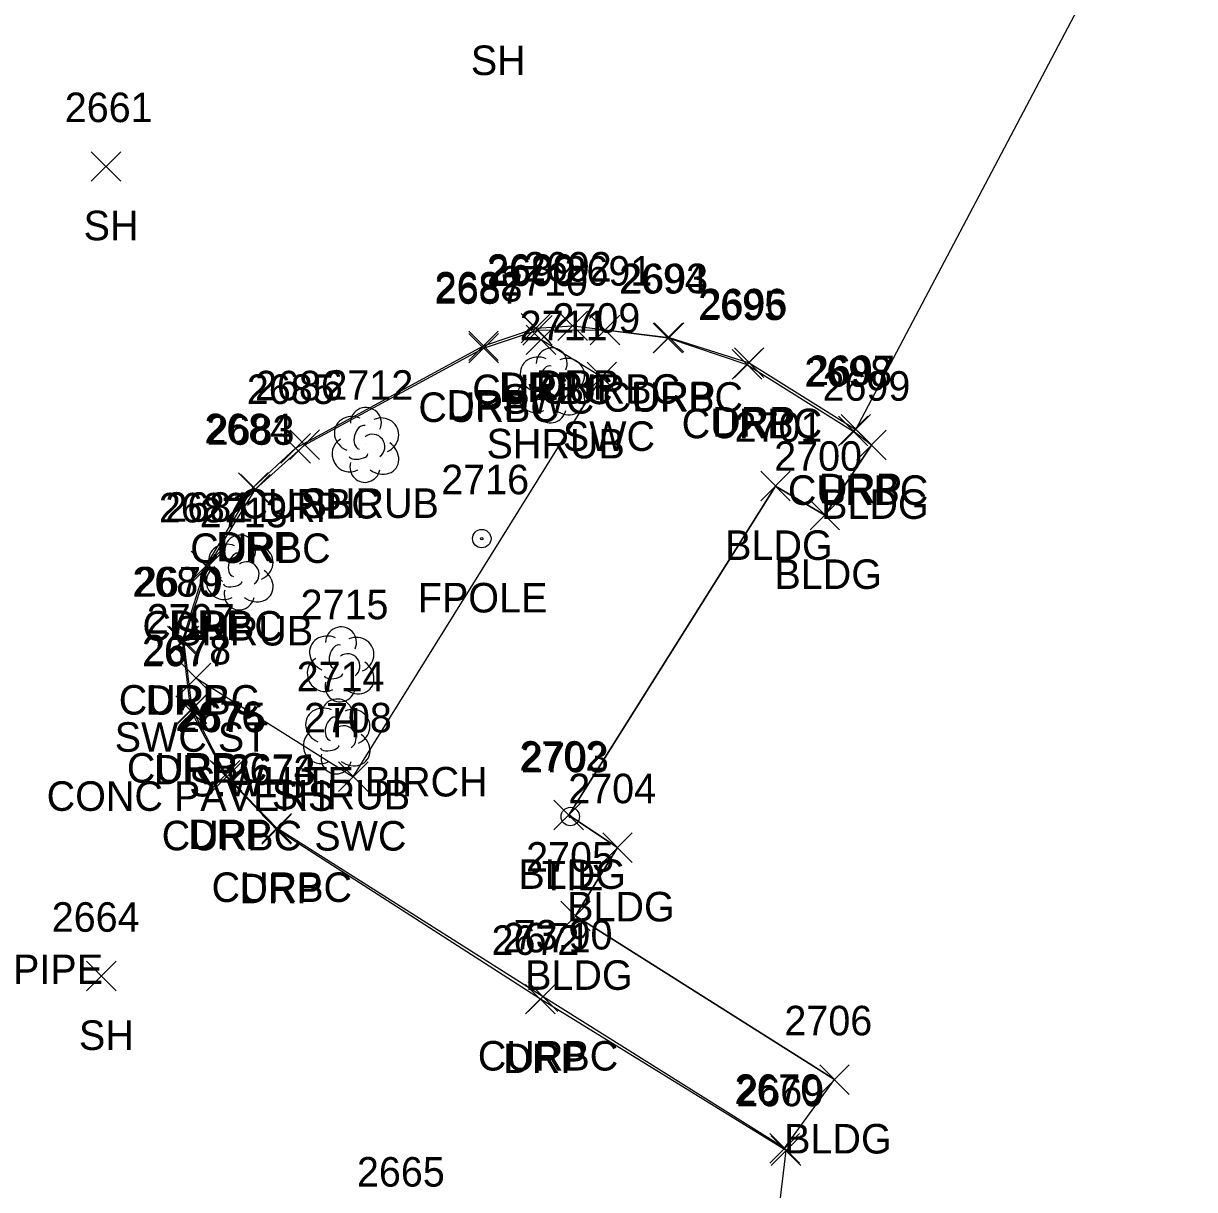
# Model space of a CAD drawing. Extents: x 1769141 to 1770911, y 735471 to 741449.
# Drawn here: x 1770697.4 to 1770776.7, y 737070.7 to 737149.7 of the extents above; entities that cross this region are included whole.
import ezdxf

# ---------------------------------------------------------------- set-up
doc = ezdxf.new("R2010")
doc.units = 0
for name, color, linetype in [('C_A', 7, 'Continuous'), ('C_C', 7, 'Continuous'), ('C_I', 7, 'Continuous'), ('CBP', 7, 'Continuous'), ('D_C', 7, 'Continuous'), ('L_A', 7, 'Continuous'), ('L_C', 7, 'Continuous'), ('L_I', 7, 'Continuous'), ('L_TIC', 7, 'Continuous'), ('LBC', 7, 'Continuous'), ('LFP', 7, 'Continuous'), ('LSH', 7, 'Continuous'), ('LSOGP', 7, 'Continuous'), ('LTD', 7, 'Continuous'), ('R_A', 7, 'Continuous'), ('R_C', 7, 'Continuous'), ('R_I', 7, 'Continuous'), ('R_TIC', 7, 'Continuous'), ('RC', 7, 'Continuous'), ('RDP', 7, 'Continuous'), ('RSW', 7, 'Continuous')]:
    doc.layers.add(name, color=color, linetype=linetype)

msp = doc.modelspace()

# ---------------------------------------------------------------- linework, layer by layer
at = {"layer": 'CBP'}
for radius in [0.625, 0.0833]:
    msp.add_circle((1770734.388, 737095.961), radius, dxfattribs=at)
at = {"layer": 'L_TIC'}
for points in [[(1770701.944, 737138.979), (1770703.944, 737140.979)], [(1770703.944, 737138.979), (1770701.944, 737140.979)], [(1770753.785, 737120.115), (1770755.785, 737122.115)], [(1770755.785, 737120.115), (1770753.785, 737122.115)], [(1770747.286, 737117.337), (1770749.286, 737119.337)], [(1770749.286, 737117.337), (1770747.286, 737119.337)], [(1770750.624, 737115.373), (1770752.624, 737117.373)], [(1770752.624, 737115.373), (1770750.624, 737117.373)], [(1770733.283, 737095.064), (1770735.283, 737097.064)], [(1770735.283, 737095.064), (1770733.283, 737097.064)], [(1770736.589, 737092.861), (1770738.589, 737094.861)], [(1770738.589, 737092.861), (1770736.589, 737094.861)], [(1770733.739, 737088.229), (1770735.739, 737090.229)], [(1770735.739, 737088.229), (1770733.739, 737090.229)], [(1770701.627, 737084.16), (1770703.627, 737086.16)], [(1770703.627, 737084.16), (1770701.627, 737086.16)], [(1770751.282, 737077.148), (1770753.282, 737079.148)], [(1770753.282, 737077.148), (1770751.282, 737079.148)]]:
    msp.add_lwpolyline(points, dxfattribs=at)
at = {"layer": 'LBC'}
msp.add_lwpolyline([(1770754.785, 737121.115), (1770751.624, 737116.373), (1770748.286, 737118.337), (1770734.283, 737096.064), (1770737.589, 737093.861), (1770734.739, 737089.229), (1770752.282, 737078.148)], dxfattribs=at)
at = {"layer": 'LFP'}
for radius in [0.625, 0.0833]:
    msp.add_circle((1770728.396, 737114.781), radius, dxfattribs=at)
at = {"layer": 'LSH'}
for p, q in [((1770733.087, 737125.212), (1770733.087, 737125.212)), ((1770733.087, 737125.212), (1770733.087, 737125.212)), ((1770720.501, 737121.18), (1770720.501, 737121.18)), ((1770720.501, 737121.18), (1770720.501, 737121.18)), ((1770711.987, 737112.544), (1770711.987, 737112.544)), ((1770711.987, 737112.544), (1770711.987, 737112.544)), ((1770718.551, 737101.44), (1770718.551, 737101.44)), ((1770718.551, 737101.44), (1770718.551, 737101.44))]:
    msp.add_line(p, q, dxfattribs=at)
for centre in [(1770733.134, 737126.646), (1770720.547, 737122.614), (1770712.034, 737113.978), (1770718.598, 737102.874)]:
    msp.add_arc(centre, 1.047, 335.52715, 180.95627, dxfattribs=at)
for centre, major_axis, ratio, start_param, end_param in [((1770732.295, 737125.879), (1.21, -0.512), 0.895232, 1.570796, 4.712389), ((1770734.129, 737125.796), (-1.141, -0.483), 0.949671, 1.570796, 4.712389), ((1770732.879, 737125.671), (-0.208, -0.792), 0.645439, 3.141593, 6.283185), ((1770732.004, 737124.504), (0.584, -1.042), 0.959034, 3.141593, 6.283185), ((1770733.587, 737125.046), (-0.5, 0.667), 0.989748, 3.141593, 6.283185), ((1770734.087, 737124.379), (-1.09, 0.792), 0.841452, 1.570796, 4.712389), ((1770733.087, 737123.712), (0.265, 1.061), 0.942809, 1.570796, 4.712389), ((1770732.629, 737124.462), (-0.625, -0.083), 0.423636, 0, 3.141593), ((1770719.709, 737121.846), (1.21, -0.512), 0.895232, 1.570796, 4.712389), ((1770720.292, 737121.638), (-0.208, -0.792), 0.645439, 3.141593, 6.283185), ((1770721.542, 737121.763), (-1.141, -0.483), 0.949671, 1.570796, 4.712389), ((1770721.001, 737121.013), (-0.5, 0.667), 0.989748, 3.141593, 6.283185), ((1770719.417, 737120.471), (0.584, -1.042), 0.959034, 3.141593, 6.283185), ((1770721.501, 737120.347), (-1.09, 0.792), 0.841452, 1.570796, 4.712389), ((1770720.043, 737120.43), (-0.625, -0.083), 0.423636, 0, 3.141593), ((1770720.501, 737119.68), (0.265, 1.061), 0.942809, 1.570796, 4.712389), ((1770711.195, 737113.211), (1.21, -0.512), 0.895232, 1.570796, 4.712389), ((1770713.029, 737113.128), (-1.141, -0.483), 0.949671, 1.570796, 4.712389), ((1770711.779, 737113.002), (-0.208, -0.792), 0.645439, 3.141593, 6.283185), ((1770710.904, 737111.835), (0.584, -1.042), 0.959034, 3.141593, 6.283185), ((1770712.487, 737112.377), (-0.5, 0.667), 0.989748, 3.141593, 6.283185), ((1770712.987, 737111.711), (-1.09, 0.792), 0.841452, 1.570796, 4.712389), ((1770711.987, 737111.044), (0.265, 1.061), 0.942809, 1.570796, 4.712389), ((1770711.529, 737111.794), (-0.625, -0.083), 0.423636, 0, 3.141593), ((1770717.759, 737102.106), (1.21, -0.512), 0.895232, 1.570796, 4.712389), ((1770719.593, 737102.023), (-1.141, -0.483), 0.949671, 1.570796, 4.712389), ((1770718.343, 737101.898), (-0.208, -0.792), 0.645439, 3.141593, 6.283185), ((1770717.468, 737100.731), (0.584, -1.042), 0.959034, 3.141593, 6.283185), ((1770719.051, 737101.273), (-0.5, 0.667), 0.989748, 3.141593, 6.283185), ((1770719.551, 737100.607), (-1.09, 0.792), 0.841452, 1.570796, 4.712389), ((1770718.552, 737099.94), (0.265, 1.061), 0.942809, 1.570796, 4.712389), ((1770718.093, 737100.69), (-0.625, -0.083), 0.423636, 0, 3.141593)]:
    msp.add_ellipse(centre, major_axis=major_axis, ratio=ratio, start_param=start_param, end_param=end_param, dxfattribs=at)
at = {"layer": 'LSOGP'}
msp.add_lwpolyline([(1770727.551, 736987.062), (1770734.29, 737001.021), (1770737.548, 737004.988), (1770730.074, 737009.624), (1770731.782, 737015.296), (1770733.491, 737020.967), (1770734.181, 737023.809), (1770738.175, 737038.36), (1770746.538, 737052.758), (1770748.997, 737073.345), (1770748.904, 737073.503), (1770752.282, 737078.148), (1770734.739, 737089.229), (1770737.589, 737093.861), (1770734.283, 737096.064), (1770748.286, 737118.337), (1770751.624, 737116.373), (1770754.785, 737121.115), (1770753.542, 737122.064), (1770753.723, 737122.177), (1770776.665, 737165.642)], dxfattribs=at)
at = {"layer": 'LTD'}
msp.add_line((1770718.819, 737106.321), (1770718.819, 737106.321), dxfattribs=at)
msp.add_line((1770718.819, 737106.321), (1770718.819, 737106.321), dxfattribs=at)
msp.add_arc((1770718.866, 737107.755), 1.047, 335.52715, 180.95627, dxfattribs=at)
for centre, major_axis, ratio, start_param, end_param in [((1770718.027, 737106.987), (1.21, -0.512), 0.895232, 1.570796, 4.712389), ((1770719.861, 737106.904), (-1.141, -0.483), 0.949671, 1.570796, 4.712389), ((1770718.611, 737106.779), (-0.208, -0.792), 0.645439, 3.141593, 6.283185), ((1770717.736, 737105.612), (0.584, -1.042), 0.959034, 3.141593, 6.283185), ((1770719.319, 737106.154), (-0.5, 0.667), 0.989748, 3.141593, 6.283185), ((1770719.819, 737105.488), (-1.09, 0.792), 0.841452, 1.570796, 4.712389), ((1770718.819, 737104.821), (0.265, 1.061), 0.942809, 1.570796, 4.712389), ((1770718.361, 737105.571), (-0.625, -0.083), 0.423636, 0, 3.141593)]:
    msp.add_ellipse(centre, major_axis=major_axis, ratio=ratio, start_param=start_param, end_param=end_param, dxfattribs=at)
at = {"layer": 'R_TIC'}
for points in [[(1770731.055, 737128.031), (1770733.055, 737130.031)], [(1770733.055, 737128.031), (1770731.055, 737130.031)], [(1770731.169, 737127.885), (1770733.169, 737129.885)], [(1770733.169, 737127.885), (1770731.169, 737129.885)], [(1770733.552, 737128.183), (1770735.552, 737130.183)], [(1770735.552, 737128.183), (1770733.552, 737130.183)], [(1770735.735, 737127.909), (1770737.735, 737129.909)], [(1770737.735, 737127.909), (1770735.735, 737129.909)], [(1770727.509, 737126.832), (1770729.509, 737128.832)], [(1770729.509, 737126.832), (1770727.509, 737128.832)], [(1770731.408, 737127.238), (1770733.408, 737129.238)], [(1770733.408, 737127.238), (1770731.408, 737129.238)], [(1770739.993, 737127.37), (1770741.993, 737129.37)], [(1770741.993, 737127.37), (1770739.993, 737129.37)], [(1770740.079, 737127.398), (1770742.079, 737129.398)], [(1770742.079, 737127.398), (1770740.079, 737129.398)], [(1770727.522, 737126.678), (1770729.522, 737128.678)], [(1770729.522, 737126.678), (1770727.522, 737128.678)], [(1770745.35, 737125.576), (1770747.35, 737127.576)], [(1770747.35, 737125.576), (1770745.35, 737127.576)], [(1770745.503, 737125.693), (1770747.503, 737127.693)], [(1770747.503, 737125.693), (1770745.503, 737127.693)], [(1770735.526, 737124.719), (1770737.526, 737126.719)], [(1770737.526, 737124.719), (1770735.526, 737126.719)], [(1770752.723, 737121.177), (1770754.723, 737123.177)], [(1770754.723, 737121.177), (1770752.723, 737123.177)], [(1770752.542, 737121.064), (1770754.542, 737123.064)], [(1770754.542, 737121.064), (1770752.542, 737123.064)], [(1770714.792, 737119.898), (1770716.792, 737121.898)], [(1770716.792, 737119.898), (1770714.792, 737121.898)], [(1770715.402, 737120.141), (1770717.402, 737122.141)], [(1770717.402, 737120.141), (1770715.402, 737122.141)], [(1770711.916, 737117.233), (1770713.916, 737119.233)], [(1770713.916, 737117.233), (1770711.916, 737119.233)], [(1770712.07, 737117.131), (1770714.07, 737119.131)], [(1770714.07, 737117.131), (1770712.07, 737119.131)], [(1770708.706, 737111.919), (1770710.706, 737113.919)], [(1770710.706, 737111.919), (1770708.706, 737113.919)], [(1770708.834, 737111.876), (1770710.834, 737113.876)], [(1770710.834, 737111.876), (1770708.834, 737113.876)], [(1770707.122, 737106.851), (1770709.122, 737108.851)], [(1770709.122, 737106.851), (1770707.122, 737108.851)], [(1770707.23, 737106.862), (1770709.23, 737108.862)], [(1770709.23, 737106.862), (1770707.23, 737108.862)], [(1770708.042, 737104.348), (1770710.042, 737106.348)], [(1770710.042, 737104.348), (1770708.042, 737106.348)], [(1770707.685, 737102.137), (1770709.685, 737104.137)], [(1770709.685, 737102.137), (1770707.685, 737104.137)], [(1770707.778, 737102.258), (1770709.778, 737104.258)], [(1770709.778, 737102.258), (1770707.778, 737104.258)], [(1770710.011, 737097.755), (1770712.011, 737099.755)], [(1770712.011, 737097.755), (1770710.011, 737099.755)], [(1770710.136, 737097.676), (1770712.136, 737099.676)], [(1770712.136, 737097.676), (1770710.136, 737099.676)], [(1770718.694, 737097.658), (1770720.694, 737099.658)], [(1770720.694, 737097.658), (1770718.694, 737099.658)], [(1770713.494, 737094.091), (1770715.494, 737096.091)], [(1770715.494, 737094.091), (1770713.494, 737096.091)], [(1770713.517, 737094.178), (1770715.517, 737096.178)], [(1770715.517, 737094.178), (1770713.517, 737096.178)], [(1770731.362, 737082.595), (1770733.362, 737084.595)], [(1770733.362, 737082.595), (1770731.362, 737084.595)], [(1770731.545, 737082.764), (1770733.545, 737084.764)], [(1770733.545, 737082.764), (1770731.545, 737084.764)], [(1770747.904, 737072.503), (1770749.904, 737074.503)], [(1770749.904, 737072.503), (1770747.904, 737074.503)], [(1770747.997, 737072.345), (1770749.997, 737074.345)], [(1770749.997, 737072.345), (1770747.997, 737074.345)]]:
    msp.add_lwpolyline(points, dxfattribs=at)
at = {"layer": 'RC'}
msp.add_lwpolyline([(1770748.904, 737073.503), (1770732.545, 737083.764), (1770714.517, 737095.178), (1770711.136, 737098.676), (1770708.778, 737103.258), (1770708.23, 737107.862), (1770709.834, 737112.876), (1770713.07, 737118.131), (1770716.402, 737121.141), (1770728.522, 737127.678), (1770732.169, 737128.885), (1770736.735, 737128.909), (1770740.993, 737128.37), (1770746.35, 737126.576), (1770753.542, 737122.064)], dxfattribs=at)
at = {"layer": 'RDP'}
msp.add_lwpolyline([(1770748.997, 737073.345), (1770732.362, 737083.595), (1770714.494, 737095.091), (1770711.011, 737098.755), (1770708.685, 737103.137), (1770708.122, 737107.851), (1770709.706, 737112.919), (1770712.916, 737118.233), (1770715.792, 737120.898), (1770728.509, 737127.832), (1770732.055, 737129.031), (1770734.552, 737129.183), (1770741.079, 737128.398), (1770746.503, 737126.693), (1770753.723, 737122.177)], dxfattribs=at)
at = {"layer": 'RSW'}
msp.add_lwpolyline([(1770709.042, 737105.348), (1770719.694, 737098.658), (1770736.526, 737125.719), (1770732.408, 737128.238)], dxfattribs=at)

# ---------------------------------------------------------------- texts
at = {"layer": 'C_A'}
msp.add_text('TIE', height=2, dxfattribs=at).set_placement((1770732.467, 737090.961))
at = {"layer": 'C_C'}
msp.add_text('73.90', height=2, dxfattribs=at).set_placement((1770730.554, 737086.961))
at = {"layer": 'C_I'}
msp.add_text('2703', height=2, dxfattribs=at).set_placement((1770731.05, 737098.961))
at = {"layer": 'D_C'}
msp.add_text('UNABLE TO LOCATE OUTLET PIPE', height=2, dxfattribs=at).set_placement((1770658.011, 737084.618))
at = {"layer": 'L_A'}
for s, p in [('SH', (1770727.654, 737146.167)), ('SH', (1770701.432, 737134.979)), ('SHRUB', (1770728.717, 737120.212)), ('SHRUB', (1770716.131, 737116.18)), ('BLDG', (1770751.375, 737116.115)), ('BLDG', (1770744.877, 737113.337)), ('BLDG', (1770748.214, 737111.373)), ('FPOLE', (1770724.066, 737109.781)), ('SHRUB', (1770707.617, 737107.544)), ('H', (1770718.252, 737101.321)), ('SHRUB', (1770714.181, 737096.44)), ('BLDG', (1770730.873, 737091.064)), ('BLDG', (1770734.179, 737088.861)), ('BLDG', (1770731.33, 737084.229)), ('SH', (1770701.115, 737080.16)), ('BLDG', (1770748.873, 737073.148))]:
    msp.add_text(s, height=2, dxfattribs=at).set_placement(p)
at = {"layer": 'L_C'}
msp.add_text('S.WHITE BIRCH', height=2, dxfattribs=at).set_placement((1770708.583, 737097.321))
at = {"layer": 'L_I'}
for s, p in [('2661', (1770700.156, 737142.979)), ('2711', (1770730.961, 737128.212)), ('2712', (1770717.808, 737124.18)), ('2699', (1770751.47, 737124.115)), ('2701', (1770745.514, 737121.337)), ('2700', (1770748.198, 737119.373)), ('2716', (1770725.648, 737117.781)), ('2713', (1770709.294, 737115.544)), ('2715', (1770716.126, 737109.321)), ('2714', (1770715.858, 737104.44)), ('2702', (1770730.944, 737099.064)), ('2704', (1770734.25, 737096.861)), ('2705', (1770731.4, 737092.229)), ('2664', (1770699.273, 737088.16)), ('2706', (1770748.888, 737081.148)), ('2665', (1770719.941, 737070.906))]:
    msp.add_text(s, height=2, dxfattribs=at).set_placement(p)
at = {"layer": 'R_A'}
for s, p in [('CURBC', (1770727.752, 737123.885)), ('DRP', (1770729.543, 737124.031)), ('DRP', (1770732.04, 737124.183)), ('CURBC', (1770732.317, 737123.909)), ('DRP', (1770725.997, 737122.832)), ('SWC', (1770729.77, 737123.238)), ('CURBC', (1770736.575, 737123.37)), ('DRP', (1770738.568, 737123.398)), ('CURBC', (1770724.105, 737122.678)), ('CURBC', (1770741.933, 737121.576)), ('DRP', (1770743.991, 737121.693)), ('SWC', (1770733.888, 737120.719)), ('CURBC', (1770749.125, 737117.064)), ('DRP', (1770751.211, 737117.177)), ('CURBC', (1770711.985, 737116.141)), ('DRP', (1770713.28, 737115.898)), ('DRP', (1770710.404, 737113.233)), ('CURBC', (1770708.652, 737113.131)), ('CURBC', (1770705.416, 737107.876)), ('DRP', (1770707.195, 737107.919)), ('CURBC', (1770703.812, 737102.862)), ('DRP', (1770705.611, 737102.851)), ('SWC ST', (1770703.538, 737100.348)), ('CURBC', (1770704.36, 737098.258)), ('DRP', (1770706.174, 737098.137)), ('CURBC', (1770706.719, 737093.676)), ('DRP', (1770708.499, 737093.755)), ('SWC', (1770717.056, 737093.658)), ('CURBC', (1770710.099, 737090.178)), ('DRP', (1770711.982, 737090.091)), ('CURBC', (1770728.127, 737078.764)), ('DRP', (1770729.85, 737078.595))]:
    msp.add_text(s, height=2, dxfattribs=at).set_placement(p)
at = {"layer": 'R_C'}
msp.add_text('CONC PAVERS', height=2, dxfattribs=at).set_placement((1770698.931, 737096.348))
at = {"layer": 'R_I'}
for s, p in [('2689', (1770728.74, 737132.031)), ('2690', (1770728.776, 737131.885)), ('2692', (1770731.245, 737132.183)), ('2691', (1770733.995, 737131.909)), ('2688', (1770725.202, 737130.832)), ('2687', (1770725.215, 737130.678)), ('2710', (1770729.628, 737131.238)), ('2694', (1770737.686, 737131.37)), ('2693', (1770737.772, 737131.398)), ('2695', (1770743.043, 737129.576)), ('2696', (1770743.141, 737129.693)), ('2709', (1770733.179, 737128.719)), ('2697', (1770750.416, 737125.177)), ('2698', (1770750.235, 737125.064)), ('2685', (1770712.485, 737123.898)), ('2686', (1770713.04, 737124.141)), ('2684', (1770709.609, 737121.233)), ('2683', (1770709.763, 737121.131)), ('2682', (1770706.527, 737115.876)), ('2681', (1770706.966, 737115.919)), ('2680', (1770704.729, 737110.851)), ('2679', (1770704.915, 737110.862)), ('2707', (1770705.703, 737108.348)), ('2677', (1770705.378, 737106.137)), ('2678', (1770705.471, 737106.258)), ('2676', (1770707.649, 737101.755)), ('2675', (1770707.829, 737101.676)), ('2708', (1770716.355, 737101.658)), ('2674', (1770711.209, 737098.178)), ('2673', (1770711.187, 737098.091)), ('2672', (1770729.055, 737086.595)), ('2671', (1770729.805, 737086.764)), ('2670', (1770745.51, 737076.503)), ('2669', (1770745.635, 737076.345))]:
    msp.add_text(s, height=2, dxfattribs=at).set_placement(p)

doc.saveas('drawing.dxf')
